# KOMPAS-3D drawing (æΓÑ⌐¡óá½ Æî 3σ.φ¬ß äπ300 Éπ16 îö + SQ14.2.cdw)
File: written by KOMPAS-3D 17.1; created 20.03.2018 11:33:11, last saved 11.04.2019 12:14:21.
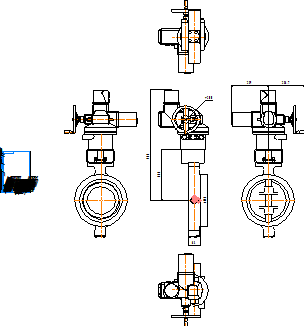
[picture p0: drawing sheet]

Sheet 1: A4, portrait

Title block, sheet 1: name: Стейнвал ТМ 3х.экс / Ду300 Ру16 МФ + SQ14.2; material: Внимание! Данный продукт является объектом авторского права ООО «Торговый Дом АДЛ». / Запрещается изменение, копирование, распространение / (в том числе путем копирования на другие сайты и ресурсы в Интернете) / или любое иное использование информации и объектов без предварительного / согласия правообладателя (ООО «Торговый Дом АДЛ»).; mass: 97,3; sheets: 1; organisation: ООО "Торговый дом АДЛ"; sheet format: A4; stored path: \\adlc.lan\data\АДЛ_ПКД\3D-модели\ADL production\Дисковые поворотные затворы СТЕЙНВАЛ\Трехэксцентриковый\Стейнвал м-ф\С эл.приводом\KOMPAS 2D\Стейнвал ТМ 3х.экс Ду300 Ру16 МФ + SQ14.2.cdw

Views: Вид 1, Проекционный вид 2, Проекционный вид 3, Проекционный вид 4, Проекционный вид 5
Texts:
  kka
  adl
Dimensions and other numbers on the sheet: 365; 785; 83; 375; 200; 258,7; 259; 1:1; 1; 97,3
